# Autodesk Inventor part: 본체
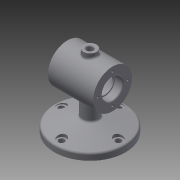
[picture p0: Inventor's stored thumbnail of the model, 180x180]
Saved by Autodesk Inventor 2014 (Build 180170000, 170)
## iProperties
Created: 2018-12
Part Number: 본체
Material: Generic
Document SubType Name: Modeling
Designer: kh
Density: 1 g/cm^3
Appearance: Default
Author: kh
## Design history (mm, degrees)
sketch "Sketch1"
  geometry: C1 r 55 at (0, 0); 1 further point
  constraints: 1 centre point, 1 coincident
  dimensions: "d0" = 110 diameter of C1
extrude "Extrusion1" new body sketch "Sketch1" distance "d1" = 10; taper "d2" = 0 deg
sketch "Sketch2"
  geometry: L1 (55, 10)-(-55, 10) reference; L2 (-55, 0)-(55, 0) reference; L3 (35, 75)-(-35, 75); L4 (0, 0)-(0, 161.795); L5 (0, 0)-(0, 75); L6 (35, 75)-(35, 105); L7 (35, 105)-(-35, 105); L8 (-35, 105)-(-35, 75)
  constraints: 12 end point, 3 parallel, 2 perpendicular, 1 midpoint, 1 point on line
  dimensions: "d3" = 70 distance of L3.start L3.end; "d4" = 75 distance of L5.end L4.start; "d5" = 60 diameter of L7 L3
revolve "Revolution1" sketch "Sketch2" stored, may be unused: angle "d6" = 90 deg
sketch "Sketch3"
  geometry: L1 (35, 45)-(35, 105) reference; L2 (-35, 45)-(-35, 105) reference; L3 (35, 75)-(-35, 75); L4 (35, 91)-(23, 91); L5 (23, 91)-(23, 89); L6 (23, 89)-(20, 89); L7 (20, 89)-(20, 100); L8 (20, 100)-(-20, 100); L9 (-20, 100)-(-20, 89); L10 (-20, 89)-(-23, 89); L11 (-23, 89)-(-23, 91); L12 (-23, 91)-(-35, 91); L13 (0, 75)-(0, 112.28); L14 (35, 91)-(35, 75); L15 (-35, 91)-(-35, 75); 2 further points
  constraints: 26 end point, 7 parallel, 4 midpoint, 4 perpendicular, 3 point on line, 1 collinear
  dimensions: "d7" = 32 diameter of L4 L3; "d8" = 28 diameter of L6 L3; "d9" = 50 diameter of L8 L3; "d10" = 28 diameter of L10 L3; "d11" = 32 diameter of L12 L3; "d12" = 40 distance of L8.end L7.end; "d13" = 3 horizontal distance of L7.end L4.end; "d14" = 3 distance of L10.end L9.end
revolve "Revolution2" sketch "Sketch3" stored, may be unused: angle "d15" = 90 deg
chamfer "Chamfer1" distance "d16" = 1; stored, may be unused: second distance "d17" = 2, angle "d18" = 45 deg
fillet "Fillet1" dims "d19" = 3
fillet "Fillet2" dims "d20" = 0.3
workplane "Work Plane1"
sketch "Sketch4"
  geometry: C1 r 10 at (0, 0); 1 further point
  constraints: 1 centre point, 1 coincident
  dimensions: "d23" = 20 diameter of C1
extrude "Extrusion2" join sketch "Sketch4" stored distance "d24" = 0; taper "d25" = 0 deg
sketch "Sketch5"
  geometry: C1 r 5 at (0, 0); 1 further point
  constraints: 1 centre point, 1 coincident
  dimensions: "d26" = 10 diameter of C1
extrude "Extrusion3" cut sketch "Sketch5" stored distance "d27" = 10; taper "d28" = 0 deg
sketch "Sketch6"
  geometry: C1 r 55 at (0, 0) reference; C2 r 55 at (0, 0); 1 further point
  constraints: 1 centre point, 1 coincident, 1 concentric
extrude "Extrusion4" join sketch "Sketch6" distance "d29" = 30; taper "d30" = -75 deg
sketch "Sketch7"
  geometry: C1 r 55 at (0, 0) reference; C2 r 12 at (0, 0); 1 further point
  constraints: 1 centre point, 1 coincident
  dimensions: "d31" = 24 diameter of C2
extrude "Extrusion5" join sketch "Sketch7" stored distance "d32" = 24 (= d31); taper "d33" = 0 deg
sketch "Sketch8"
  geometry: L1 (0, 0)-(0, -55); L2 (0, 0)-(-44, 0); L3 (0, 44)-(0, 0); L4 (44, 0)-(0, 0); A1 r 44 centre (0, 0) between (0, -44) and (-44, 0); 4 further points
  constraints: 8 end point, 4 coincident, 4 point on circle, 2 perpendicular, 1 centre point, 1 collinear, 1 point on line, 1 vertical, 1 vertical alignment, 1 other
  dimensions: "d34" = 88 diameter of A1
hole "Hole1" sketch "Sketch8" at (0, -44), (-44, 0), (0, 44), (44, 0) diameter "d35" = 9; stored, may be unused: countersink angle "d39" = 82 deg, drill point angle "d41" = 118 deg; dims "d36" = 6, "d37" = 3.023, "d38" = 2, "d40" = 8
workplane "Work Plane2"
sketch "Sketch9"
  geometry: C1 r 4.5 at (0, 44) reference; C2 r 4.5 at (0, -44) reference; C3 r 4.5 at (44, 0) reference; C4 r 4.5 at (-44, 0) reference; C5 r 55 at (0, 0) reference; C6 r 7 at (-44, 0); 1 further point
  constraints: 1 centre point, 1 coincident
  dimensions: "d43" = 14 diameter of C6
extrude "Extrusion6" cut sketch "Sketch9" distance "d44" = 10; taper "d45" = 0 deg
pattern_circular "Circular Pattern1" dims angle "d47" = 360 deg
fillet "Fillet4" dims "d49" = 3
chamfer "Chamfer2" distance "d50" = 1; stored, may be unused: second distance "d51" = 2, angle "d52" = 45 deg
sketch "Sketch10" dims "d53" = 46
  geometry: L1 (0, 0)-(-23, 0); C1 r 30 at (0, 0) reference; C2 r 17 at (0, 0) reference; 2 further points
  constraints: 2 coincident, 2 end point, 1 horizontal, 1 horizontal alignment, 2 other
hole "Hole2" sketch "Sketch10" at (-23, 0) diameter "d54" = 3.242; stored, may be unused: countersink angle "d58" = 82 deg, drill point angle "d60" = 118 deg; dims "d55" = 8, "d56" = 3.023, "d57" = 2, "d59" = 10
pattern_circular "Circular Pattern2" dims angle "d62" = 360 deg
mirror "Mirror1"
workplane "Work Plane3"
sketch "Sketch11" dims "d1" = 10, "d2" = 0
  geometry: L1 (-35, 45)-(-35, 105) reference; L2 (-35, 45)-(35, 45) reference; L3 (-58.579, 83.479)-(58.579, 83.479); L4 (58.579, 83.479)-(58.579, 66.521); L5 (58.579, 66.521)-(-58.579, 66.521); L6 (-58.579, 66.521)-(-58.579, 83.479); L7 (-58.579, 83.479)-(58.579, 66.521); 1 further point
  constraints: 2 end point, 2 other
emboss "Emboss1" sketch "Sketch11" dims "d7" = 32, "d8" = 28, "d9" = 50, "d10" = 28, "d11" = 32, "d12" = 40, "d13" = 3, "d14" = 3, "d66" = 0.5, "d67" = 0
body "Solid1"
node "Projected Loop1"
node "Projected Loop2"
node "Projected Loop3"
node "Projected Loop4"
node "Projected Loop5"
node "Projected Loop6"
node "Projected Loop7"
other parameters: "d22" = 112, "d64" = 64.25
